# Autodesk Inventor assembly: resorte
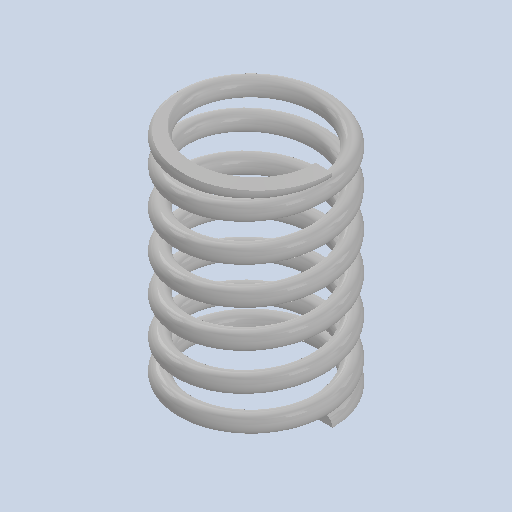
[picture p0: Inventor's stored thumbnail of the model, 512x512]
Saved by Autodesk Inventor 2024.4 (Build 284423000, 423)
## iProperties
Created: 2025-06
Part Number: resorte
Document SubType Name: Assembly
Designer: AdminForWorker
Title: resorte v2
Author: AdminForWorker
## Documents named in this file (2)
- c:\worker\convert-fusion-r02-cosv3\tmp\job-1\258\temp\files\b1f5cff6-2824-4cab-9e49-e311ea18fd89\resorte v2.iam
- c:\worker\convert-fusion-r02-cosv3\tmp\job-1\258\temp\files\b1f5cff6-2824-4cab-9e49-e311ea18fd89\94125K631_Compression Springs_1.ipt
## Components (1 placed, 1 different names)
1. 94125K631_Compression Springs:1
